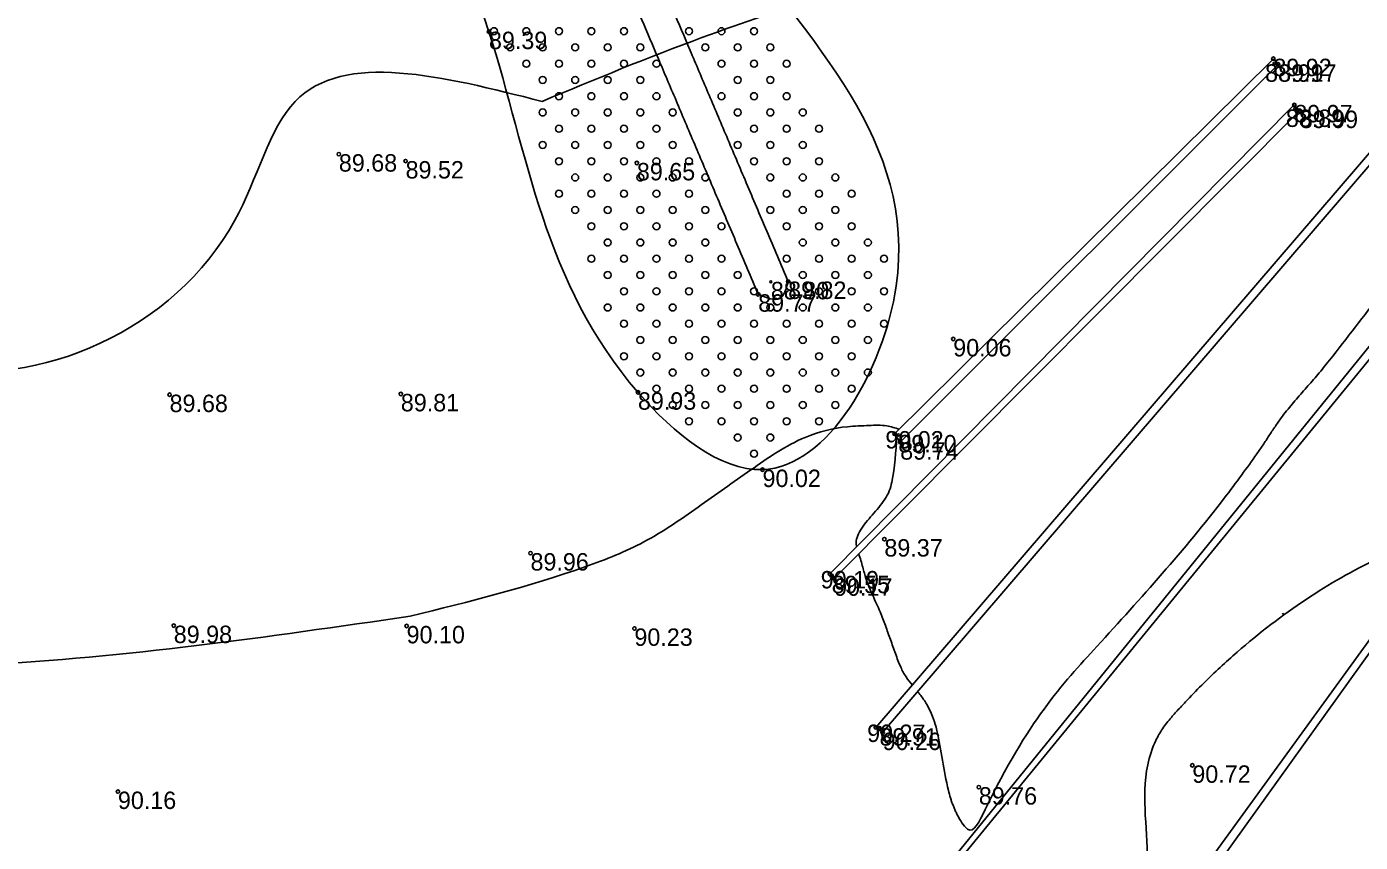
# Model space of a CAD drawing. Extents: x 316000 to 728450, y 314368 to 726000.
# Drawn here: x 726558.9 to 726846, y 316067.8 to 316243.5 of the extents above; entities that cross this region are included whole.
import ezdxf

# ---------------------------------------------------------------- set-up
doc = ezdxf.new("R2010")
doc.units = 0
for name, color, linetype in [('HIDG_ELEM_####_####_#', 7, 'Continuous'), ('HIDG_GRAV_####_####_#', 7, 'Continuous'), ('RELJ_AATZ_####_TKST_#', 7, 'Continuous'), ('RELJ_ELEM_####_####_#', 7, 'Continuous'), ('RELJ_HORZ_PAMT_####_#', 7, 'Continuous'), ('RELJ_HORZ_RESN_####_#', 7, 'Continuous'), ('TERT_ELEM_####_####_#', 7, 'Continuous'), ('TERT_KONT_####_####_#', 7, 'Continuous')]:
    doc.layers.add(name, color=color, linetype=linetype)

msp = doc.modelspace()

# ---------------------------------------------------------------- linework, layer by layer
at = {"layer": 'HIDG_ELEM_####_####_#'}
for centre in [(726827.44, 316235.55), (726831.91, 316225.81), (726719.13, 316188.51), (726746.57, 316155.55), (726732.22, 316125.23), (726742.51, 316092.41)]:
    msp.add_circle(centre, 0.225, dxfattribs=at)
at = {"layer": 'HIDG_GRAV_####_####_#'}
for points in [[(726827.3, 316236.57), (726828.34, 316235.36), (726746.97, 316153.99), (726745.77, 316155.8), (726827.3, 316236.57)], [(726731.8, 316125.64), (726831.8, 316226.62)], [(726831.8, 316226.62), (726832.97, 316225.39), (726732.74, 316124.67)], [(726855.02, 316224.51), (726741.72, 316092.54), (726743.18, 316091.45), (726856.29, 316223.31)], [(726736.1, 316036.98), (726866.31, 316197.24)], [(726866.31, 316197.24), (726867.89, 316196.14), (726737.09, 316036.39)], [(726878.01, 316152.77), (726878.91, 316151.79), (726805.97, 316050.03), (726804.2, 316051.06), (726878.01, 316152.77)], [(726731.8, 316125.64), (726732.74, 316124.67)]]:
    msp.add_lwpolyline(points, dxfattribs=at)
for points in [[(726722.84, 316188.59), (726693.65, 316257.47), (726664.46, 316326.35), (726632.07, 316402.97)], [(726716.4, 316185.85), (726687.21, 316254.73), (726658.02, 316323.61), (726625.16, 316401.2)]]:
    msp.add_open_spline(points, degree=2, dxfattribs=at)
msp.add_spline([(726722.84, 316188.59), (726721.06, 316184.96), (726716.4, 316185.85)], degree=3, dxfattribs=at)
at = {"layer": 'RELJ_ELEM_####_####_#'}
for centre in [(726658.44, 316242.39), (726827.3, 316236.57), (726828.34, 316235.36), (726831.8, 316226.62), (726832.97, 316225.39), (726626.13, 316216.01), (726640.49, 316214.53), (726690.28, 316214.13), (726722.84, 316188.59), (726716.4, 316185.85), (726758.38, 316176.22), (726589.69, 316164.23), (726639.47, 316164.39), (726690.51, 316164.74), (726745.77, 316155.8), (726746.97, 316153.99), (726717.33, 316148.09), (726743.56, 316133.12), (726667.38, 316130.11), (726731.8, 316125.64), (726732.22, 316125.23), (726732.74, 316124.67), (726590.59, 316114.49), (726640.71, 316114.43), (726689.75, 316113.89), (726741.72, 316092.54), (726742.51, 316092.41), (726743.18, 316091.45), (726809.85, 316084.4), (726578.57, 316078.76), (726763.89, 316079.71)]:
    msp.add_circle(centre, 0.375, dxfattribs=at)
at = {"layer": 'RELJ_HORZ_PAMT_####_#'}
msp.add_line((726829.23, 316117.2), (726829.52, 316116.8), dxfattribs=at)
for points in [[(726669.86, 316227.39), (726704.28, 316241.12), (726730.9, 316250.29)], [(726401.45, 316228.54), (726516.76, 316178.12), (726537.45, 316170.21), (726603.67, 316201.65), (726616.74, 316227.39), (726669.86, 316227.39)], [(726865.4, 316135.38), (726861.46, 316133.99), (726857.53, 316132.46), (726849.72, 316128.96), (726834.35, 316120.15), (726819.49, 316108.79), (726812.31, 316102.12), (726808.79, 316098.52), (726807.05, 316096.65), (726805.33, 316094.74), (726803.43, 316092.29), (726801.99, 316089.77), (726800.25, 316084.54), (726799.73, 316073.62), (726800.13, 316062.62), (726799.54, 316057.29), (726798.38, 316053.42), (726797.81, 316052.17), (726794.41, 316045.26), (726790.63, 316038.7), (726785.92, 316032.85), (726783.03, 316030.32), (726781.42, 316029.18), (726780.58, 316028.63), (726779.7, 316028.12), (726777.19, 316027), (726774.65, 316026.42), (726769.53, 316026.63), (726759.18, 316030.57), (726748.83, 316035.56), (726743.72, 316037.08), (726741.19, 316037.36), (726738.69, 316037.22), (726738.07, 316037.01), (726737.45, 316036.68), (726736.82, 316036.41), (726736.18, 316036.37), (726731.47, 316037.35)], [(727407.26, 315826.81), (727420.88, 315859.78), (727421.31, 315861.98), (727420.84, 315873.16), (727415.63, 315882.87), (727395.8, 315899.43), (727371.45, 315914.61), (727360.58, 315922.6), (727355.76, 315932.78), (727350.87, 315945.8), (727343.65, 315965.03), (727334.62, 315981.5), (727324.71, 316005.53), (727317, 316014.24), (727310.95, 316025.93), (727306.22, 316036.97), (727300.2, 316049.01), (727293.8, 316067.18), (727252.55, 316104.18), (727204.11, 316093.45), (727172.31, 316071.99), (727104.82, 316081.23), (727087.15, 316092.31), (727070.62, 316103.93), (727040.63, 316117.26), (727014.6, 316106.53), (727006.58, 316100.22), (727000.85, 316096.21), (726994.11, 316090.82), (726983.98, 316084.66), (726972.39, 316080.59), (726966.37, 316079.01), (726958.49, 316076.14), (726948.07, 316071.06), (726932.7, 316067.7), (726916.22, 316058.14), (726880.98, 316039.68), (726836.99, 316020.53), (726807.52, 316005.55), (726787.17, 315993.15), (726764.31, 315989.32), (726742.06, 315986.79), (726725.03, 315990.27), (726708.15, 315999.77), (726691.28, 316009.5), (726674.31, 316013.66), (726659.02, 316010.43), (726643.66, 316003.77), (726628.26, 315996.72), (726612.85, 315992.34), (726600.2, 315993.32), (726587.04, 315996.97), (726574, 315999.47), (726567.72, 315999.1), (726561.71, 315997.03), (726548.35, 315992.52), (726536.61, 315988.25), (726525.25, 315984.49), (726513.03, 315977.96), (726485.95, 315966.35), (726456.08, 315949.13), (726439.28, 315937.58), (726388.53, 315922.53), (726290.27, 315916.68), (726240.08, 315917.6), (726226.6, 315921.61), (726211.69, 315923.04), (726191.22, 315924.62), (726136.88, 315919.22), (726111.29, 315920.51), (726086.94, 315922.23)]]:
    msp.add_spline(points, degree=3, dxfattribs=at)
at = {"layer": 'RELJ_HORZ_RESN_####_#'}
for points in [[(726789.32, 316110.02), (726816.72, 316141.94), (726820.48, 316146.96), (726823.74, 316151.48), (726825.07, 316153.41), (726826.35, 316155.38), (726827.65, 316157.34), (726829, 316159.25), (726831.34, 316162.2), (726833.8, 316165.05), (726836.27, 316167.88), (726838.68, 316170.78), (726844.26, 316177.93), (726849.82, 316185.1), (726856.28, 316193.33), (726859.64, 316197.36), (726861.41, 316199.35), (726863.24, 316201.32), (726870.46, 316206.98), (726878.81, 316210.78), (726887.81, 316213.39), (726892.39, 316214.46), (726896.94, 316215.46), (726903.51, 316216.92), (726910.08, 316218.19), (726916.66, 316218.97), (726923.26, 316218.98), (726948.27, 316230.9)], [(726641.48, 316116.52), (726679.28, 316127.21), (726691.81, 316132.53), (726703.44, 316139.98), (726714.8, 316148.01), (726726.52, 316155.03), (726735.65, 316157.34), (726740.26, 316157.59), (726744.06, 316157.51), (726746.77, 316156.77)], [(726746.23, 316155.27), (726745.14, 316145.4), (726744.62, 316143.52), (726743.64, 316141.71), (726740.92, 316138.29), (726738.41, 316135.06), (726737.67, 316133.49), (726737.51, 316131.94), (726737.58, 316131.48)], [(726738.05, 316129.99), (726738.91, 316127.08), (726739.62, 316124.53), (726741.06, 316120.96), (726741.87, 316119.22), (726742.64, 316117.46), (726743.78, 316114.49), (726744.86, 316111.49), (726745.94, 316108.49), (726747.09, 316105.52), (726748.23, 316103.45), (726749.59, 316101.66)], [(726528.37, 316105.34), (726549.26, 316106.08), (726641.48, 316116.52)], [(726750.76, 316100.24), (726751.21, 316099.68), (726751.91, 316098.74), (726752.24, 316098.25), (726752.55, 316097.75), (726753.29, 316096.36), (726753.91, 316094.91), (726754.19, 316094.16), (726754.45, 316093.41), (726754.86, 316091.88), (726756.08, 316085.5), (726757.34, 316079), (726757.77, 316077.41), (726758.04, 316076.62), (726758.33, 316075.85), (726758.64, 316075.07), (726758.98, 316074.31), (726759.76, 316072.81), (726760.83, 316071.33), (726761.46, 316070.65), (726765.25, 316074.9), (726789.32, 316110.02)]]:
    msp.add_spline(points, degree=3, dxfattribs=at)
at = {"layer": 'TERT_ELEM_####_####_#'}
for centre in [(726659.5, 316242.5), (726666.5, 316242.5), (726673.5, 316242.5), (726680.5, 316242.5), (726687.5, 316242.5), (726701.5, 316242.5), (726708.5, 316242.5), (726715.5, 316242.5), (726663, 316239), (726670, 316239), (726677, 316239), (726684, 316239), (726691, 316239), (726705, 316239), (726712, 316239), (726719, 316239), (726666.5, 316235.5), (726673.5, 316235.5), (726680.5, 316235.5), (726687.5, 316235.5), (726694.5, 316235.5), (726708.5, 316235.5), (726715.5, 316235.5), (726722.5, 316235.5), (726670, 316232), (726677, 316232), (726684, 316232), (726691, 316232), (726712, 316232), (726719, 316232), (726673.5, 316228.5), (726680.5, 316228.5), (726687.5, 316228.5), (726694.5, 316228.5), (726708.5, 316228.5), (726715.5, 316228.5), (726722.5, 316228.5), (726670, 316225), (726677, 316225), (726684, 316225), (726691, 316225), (726698, 316225), (726712, 316225), (726719, 316225), (726726, 316225), (726673.5, 316221.5), (726680.5, 316221.5), (726687.5, 316221.5), (726694.5, 316221.5), (726715.5, 316221.5), (726722.5, 316221.5), (726729.5, 316221.5), (726670, 316218), (726677, 316218), (726684, 316218), (726691, 316218), (726698, 316218), (726712, 316218), (726719, 316218), (726726, 316218), (726673.5, 316214.5), (726680.5, 316214.5), (726687.5, 316214.5), (726694.5, 316214.5), (726701.5, 316214.5), (726715.5, 316214.5), (726722.5, 316214.5), (726729.5, 316214.5), (726677, 316211), (726684, 316211), (726691, 316211), (726698, 316211), (726705, 316211), (726719, 316211), (726726, 316211), (726733, 316211), (726673.5, 316207.5), (726680.5, 316207.5), (726687.5, 316207.5), (726694.5, 316207.5), (726701.5, 316207.5), (726722.5, 316207.5), (726729.5, 316207.5), (726736.5, 316207.5), (726677, 316204), (726684, 316204), (726691, 316204), (726698, 316204), (726705, 316204), (726719, 316204), (726726, 316204), (726733, 316204), (726680.5, 316200.5), (726687.5, 316200.5), (726694.5, 316200.5), (726701.5, 316200.5), (726708.5, 316200.5), (726722.5, 316200.5), (726729.5, 316200.5), (726736.5, 316200.5), (726684, 316197), (726691, 316197), (726698, 316197), (726705, 316197), (726726, 316197), (726733, 316197), (726740, 316197), (726680.5, 316193.5), (726687.5, 316193.5), (726694.5, 316193.5), (726701.5, 316193.5), (726708.5, 316193.5), (726722.5, 316193.5), (726729.5, 316193.5), (726736.5, 316193.5), (726743.5, 316193.5), (726684, 316190), (726691, 316190), (726698, 316190), (726705, 316190), (726712, 316190), (726726, 316190), (726733, 316190), (726740, 316190), (726687.5, 316186.5), (726694.5, 316186.5), (726701.5, 316186.5), (726708.5, 316186.5), (726715.5, 316186.5), (726729.5, 316186.5), (726736.5, 316186.5), (726743.5, 316186.5), (726684, 316183), (726691, 316183), (726698, 316183), (726705, 316183), (726712, 316183), (726719, 316183), (726726, 316183), (726733, 316183), (726740, 316183), (726687.5, 316179.5), (726694.5, 316179.5), (726701.5, 316179.5), (726708.5, 316179.5), (726715.5, 316179.5), (726722.5, 316179.5), (726729.5, 316179.5), (726736.5, 316179.5), (726743.5, 316179.5), (726691, 316176), (726698, 316176), (726705, 316176), (726712, 316176), (726719, 316176), (726726, 316176), (726733, 316176), (726740, 316176), (726687.5, 316172.5), (726694.5, 316172.5), (726701.5, 316172.5), (726708.5, 316172.5), (726715.5, 316172.5), (726722.5, 316172.5), (726729.5, 316172.5), (726736.5, 316172.5), (726691, 316169), (726698, 316169), (726705, 316169), (726712, 316169), (726719, 316169), (726726, 316169), (726733, 316169), (726740, 316169), (726694.5, 316165.5), (726701.5, 316165.5), (726708.5, 316165.5), (726715.5, 316165.5), (726722.5, 316165.5), (726729.5, 316165.5), (726736.5, 316165.5), (726698, 316162), (726705, 316162), (726712, 316162), (726719, 316162), (726726, 316162), (726733, 316162), (726701.5, 316158.5), (726708.5, 316158.5), (726715.5, 316158.5), (726722.5, 316158.5), (726729.5, 316158.5), (726712, 316155), (726719, 316155), (726715.5, 316151.5)]:
    msp.add_circle(centre, 0.75, dxfattribs=at)
at = {"layer": 'TERT_KONT_####_####_#'}
msp.add_spline([(726673.86, 316335.5), (726710.01, 316264.69), (726746.09, 316187.61), (726717.33, 316148.09), (726690.51, 316164.74), (726658.44, 316242.39), (726615.66, 316338.31), (726598.54, 316383.58)], degree=3, dxfattribs=at)

# ---------------------------------------------------------------- texts
at = {"layer": 'RELJ_AATZ_####_TKST_#'}
for s, p in [('89.39', (726658.44, 316238.64)), ('89.92', (726827.3, 316232.82)), ('88.91', (726825.5, 316231.61)), ('89.97', (726828.34, 316231.61)), ('88.89', (726829.98, 316221.88)), ('89.97', (726831.8, 316222.87)), ('89.99', (726832.97, 316221.64)), ('89.68', (726626.13, 316212.26)), ('89.52', (726640.49, 316210.78)), ('89.65', (726690.28, 316210.38)), ('88.80', (726719.12, 316184.76)), ('89.82', (726722.84, 316184.84)), ('89.77', (726716.4, 316182.1)), ('90.06', (726758.38, 316172.47)), ('89.68', (726589.69, 316160.48)), ('89.81', (726639.47, 316160.64)), ('89.93', (726690.51, 316160.99)), ('90.02', (726743.77, 316152.64)), ('89.10', (726746.57, 316151.8)), ('89.74', (726746.97, 316150.24)), ('90.02', (726717.33, 316144.34)), ('89.37', (726743.56, 316129.37)), ('89.96', (726667.38, 316126.36)), ('90.19', (726729.85, 316122.51)), ('89.55', (726732.22, 316121.48)), ('90.17', (726732.74, 316120.92)), ('89.98', (726590.59, 316110.74)), ('90.10', (726640.71, 316110.68)), ('90.23', (726689.75, 316110.14)), ('90.27', (726739.85, 316089.44)), ('89.91', (726742.51, 316088.66)), ('90.26', (726743.18, 316087.7)), ('90.72', (726809.85, 316080.65)), ('90.16', (726578.57, 316075.01)), ('89.76', (726763.89, 316075.96))]:
    msp.add_text(s, height=3.75, dxfattribs=at).set_placement(p)

doc.saveas('drawing.dxf')
